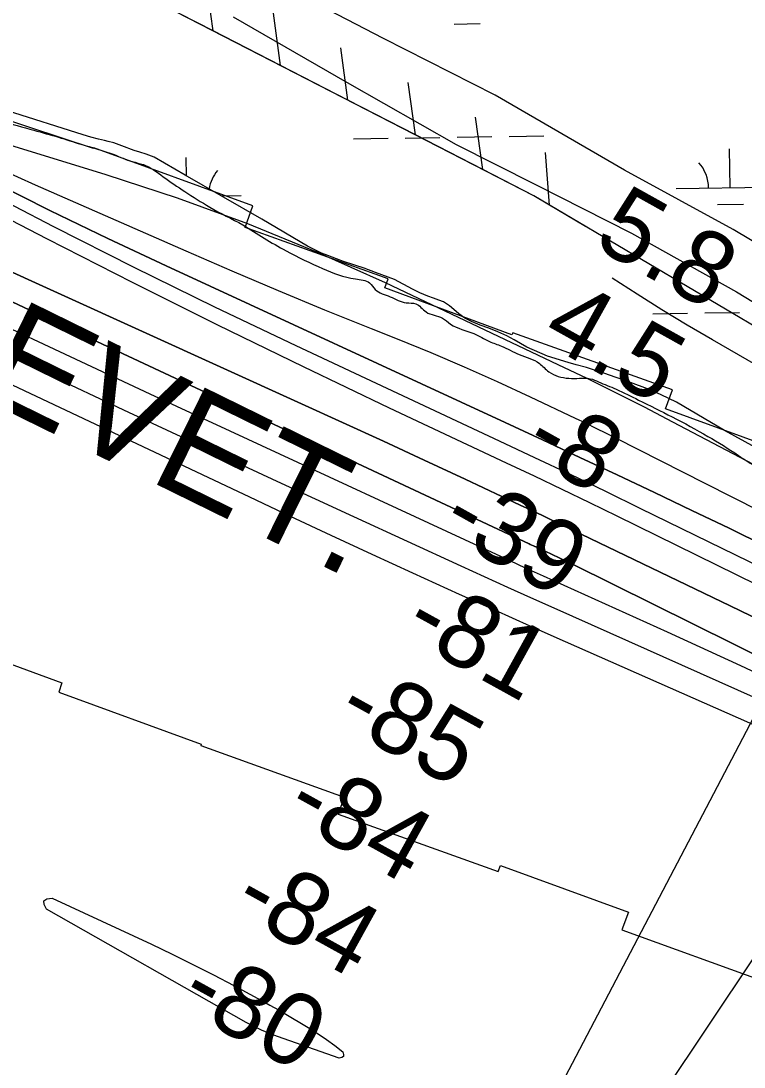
# Model space of a CAD drawing. Extents: x 3855477 to 3893699, y 299188 to 325115.
# Drawn here: x 3862374 to 3863042, y 315928 to 316895 of the extents above; entities that cross this region are included whole.
import ezdxf

# ---------------------------------------------------------------- set-up
doc = ezdxf.new("R2010")
doc.units = 0
for name, color, linetype in [('V-LEVE-TOET', 7, 'Continuous'), ('V-RIVR-EDGE', 7, 'Continuous'), ('V-RIVR-RANG', 7, 'Continuous'), ('V-ROAD-CNTR', 7, 'Continuous'), ('V-RRAP-FSHR', 7, 'Continuous'), ('V-RRAP-RVMT', 7, 'Continuous'), ('V-RRAP-RVMT-IDEN', 7, 'Continuous'), ('V-TOPO-DPTH', 7, 'Continuous'), ('V-TOPO-MAJR', 7, 'Continuous'), ('V-TOPO-MINR', 7, 'Continuous'), ('V-TOPO-WATR', 7, 'Continuous'), ('V-WETL-SWMP', 7, 'Continuous')]:
    doc.layers.add(name, color=color, linetype=linetype)

msp = doc.modelspace()

# ---------------------------------------------------------------- linework, layer by layer
at = {"layer": 'V-LEVE-TOET'}
for points in [[(3864365.02, 315977.84), (3864291.52, 316022.98), (3864202.21, 316071.98), (3864114.46, 316118.32), (3864011.47, 316172.75), (3863900.03, 316227.26), (3863792.82, 316282.79), (3863620.45, 316372.27), (3863488.09, 316447.6), (3863361.48, 316517.59), (3863231.7, 316587.09), (3863120.34, 316649.52), (3863032.12, 316702.21), (3862931.78, 316757.14), (3862812.04, 316826.53), (3862709.02, 316878.84), (3862581.85, 316945.14), (3862463.67, 317012.4), (3862350.14, 317069.05)], [(3862570.28, 316898.77), (3862675.32, 316837.98), (3862776.17, 316780.94), (3862848.7, 316744.26), (3862938.05, 316698.96), (3863035.23, 316644.59), (3863155.98, 316570.97), (3863261.65, 316519.68), (3863353.05, 316468.55), (3863460.76, 316410.37), (3863583.75, 316348.35), (3863677.77, 316295.6), (3863771.86, 316248.66), (3863851.78, 316211.38), (3863907.02, 316188.09), (3864001.5, 316127.94), (3864120.16, 316055.92), (3864180.06, 316024.66), (3864287.88, 315977.05), (3864332.62, 315960.74), (3864357.98, 315960.48), (3864374.39, 315963.48), (3864374.47, 315971.4), (3864365.02, 315977.84)]]:
    msp.add_lwpolyline(points, dxfattribs=at)
at = {"layer": 'V-RIVR-EDGE'}
for points in [[(3861643.53, 317089.49), (3861674.18, 317073.47), (3861698.46, 317060.26), (3861723.94, 317049.04), (3861744.63, 317038.63), (3861771.7, 317026.2), (3861804.75, 317012.17), (3861824.65, 317002.96), (3861840.97, 316994.15), (3861856.1, 316990.13), (3861866.47, 316990.1), (3861879.61, 316985.69), (3861900.3, 316974.08), (3861917.82, 316966.46), (3862001.43, 316931.98), (3862028.89, 316919.56), (3862036.87, 316919.94), (3862045.23, 316916.33), (3862058.76, 316907.93), (3862071.5, 316904.31), (3862089.42, 316899.08), (3862105.35, 316894.26), (3862127.64, 316884.64), (3862144.36, 316874.64), (3862154.31, 316868.24), (3862166.65, 316864.62), (3862190.95, 316859.78), (3862210.07, 316856.54), (3862236.75, 316848.9), (3862259.45, 316840.88), (3862302.44, 316817.65), (3862327.52, 316808.43), (3862335.49, 316808.41), (3862355.41, 316803.18), (3862386.07, 316793.93), (3862408.77, 316787.5), (3862429.48, 316781.07), (3862460.14, 316771.43), (3862476.86, 316765.01), (3862487.22, 316762.2), (3862505.52, 316751), (3862525.42, 316737.4), (3862548.5, 316722.99), (3862579.14, 316706.58)], [(3862579.14, 316706.58), (3862618.94, 316682.57), (3862652.77, 316666.14), (3862683.04, 316656.5), (3862696.18, 316652.88), (3862701.35, 316646.89), (3862715.28, 316640.08), (3862730.01, 316634.47), (3862738.78, 316633.65), (3862748.32, 316626.05), (3862763.45, 316620.43), (3862771.01, 316614.84), (3862792.51, 316606.02), (3862806.84, 316598.81), (3862817.99, 316594.4), (3862834.31, 316586.78), (3862853.02, 316578.37), (3862861.77, 316570.77), (3862880.08, 316564.75), (3862890.05, 316564.73), (3862900.01, 316564.3), (3862907.58, 316561.49), (3862923.9, 316554.68), (3862944.6, 316544.66), (3862975.64, 316529.04), (3863008.68, 316511.03), (3863036.93, 316493.42), (3863051.26, 316484.22), (3863059.61, 316479.82), (3863073.14, 316469.42), (3863078.7, 316461.84), (3863091.04, 316455.43), (3863113.73, 316446.6), (3863137.23, 316440.57), (3863166.3, 316430.53), (3863183.42, 316425.71), (3863207.7, 316412.1), (3863228, 316399.69), (3863238.35, 316395.68), (3863252.68, 316390.47), (3863259.44, 316385.27), (3863266.6, 316378.08), (3863269.37, 316370.9), (3863279.32, 316363.3), (3863294.44, 316355.69), (3863309.17, 316346.89), (3863343, 316331.26), (3863355.34, 316322.06), (3863380.4, 316304.47), (3863423.37, 316277.26), (3863452.02, 316258.46), (3863472.72, 316247.65), (3863532.42, 316214.82), (3863576.2, 316192.79), (3863612.02, 316173.97), (3863662.97, 316147.94), (3863701.98, 316129.91), (3863762.09, 316101.46), (3863803.49, 316080.64), (3863847.67, 316056.62), (3863876.33, 316044.19), (3863896.63, 316031.79), (3863917.72, 316020.58), (3863971.85, 315991.35), (3864020.81, 315966.12), (3864054.23, 315946.51), (3864091.65, 315926.89), (3864114.73, 315913.68), (3864131.85, 315906.86), (3864146.97, 315897.66), (3864174.04, 315883.64), (3864183.18, 315874.06), (3864194.33, 315870.44), (3864207.47, 315866.82), (3864224.19, 315858.81), (3864239.32, 315850.4), (3864262.4, 315839.98), (3864273.56, 315837.17), (3864288.68, 315830.35), (3864303.82, 315827.93), (3864315.37, 315825.11), (3864338.47, 315817.08), (3864360.77, 315810.65), (3864391.41, 315792.24), (3864418.87, 315776.23), (3864435.97, 315762.24), (3864459.04, 315741.86), (3864510.37, 315709.85), (3864535.44, 315695.84), (3864548.97, 315685.44), (3864561.3, 315675.85), (3864568.85, 315666.66), (3864582.37, 315656.66), (3864595.1, 315647.07), (3864600.67, 315641.08), (3864607.02, 315633.09), (3864612.59, 315626.3), (3864620.15, 315622.69), (3864637.27, 315615.88), (3864659.57, 315609.05), (3864678.28, 315601.03), (3864697.4, 315595.4), (3864745.56, 315571.77), (3864769.85, 315563.74), (3864787.37, 315555.73), (3864811.24, 315540.52), (3864821.2, 315537.71), (3864833.16, 315537.68), (3864842.32, 315536.46), (3864849.48, 315531.26), (3864857.43, 315522.87), (3864872.16, 315516.86), (3864908, 315506.01), (3864925.13, 315500.39), (3864937.87, 315498.76), (3864948.62, 315491.56), (3864956.98, 315489.55), (3864964.15, 315487.54), (3865017.51, 315468.28), (3865068.47, 315449.82), (3865096.34, 315439.39), (3865128.59, 315424.96), (3865154.87, 315414.93), (3865175.96, 315401.73), (3865212.19, 315385.7), (3865243.63, 315368.48), (3865263.13, 315356.48), (3865277.85, 315348.07), (3865296.96, 315338.06), (3865316.47, 315331.24), (3865337.16, 315318.04), (3865369.39, 315298.43), (3865405.2, 315275.22), (3865431.87, 315259.61), (3865448.19, 315254), (3865473.66, 315238.39), (3865499.13, 315224.78), (3865515.06, 315217.96), (3865531.77, 315209.15), (3865549.68, 315199.54), (3865571.18, 315191.52), (3865609, 315173.09), (3865653.97, 315145.48), (3865693.76, 315123.07), (3865732.77, 315101.85), (3865776.94, 315077.43), (3865798.43, 315063.82), (3865826.69, 315046.62), (3865853.35, 315032.6), (3865883.2, 315017.39), (3865895.15, 315011.38), (3865904.29, 315003.78), (3865913.04, 314994.59), (3865919.8, 314990.19), (3865927.77, 314987.38), (3865939.71, 314983.37), (3865950.47, 314980.55), (3865961.62, 314976.54), (3865977.53, 314967.34), (3866028.88, 314942.9), (3866056.75, 314928.48), (3866076.64, 314915.28), (3866096.53, 314901.68), (3866120.41, 314888.47), (3866143.9, 314878.05), (3866161.41, 314867.25), (3866178.14, 314862.82), (3866201.24, 314856.79), (3866223.14, 314850.36), (3866245.83, 314837.55), (3866263.73, 314827.14), (3866282.84, 314818.72), (3866292.41, 314818.7), (3866300.78, 314818.28), (3866309.94, 314816.27), (3866326.66, 314808.65), (3866348.53, 314791.06), (3866360.08, 314786.25), (3866377.59, 314778.64), (3866387.55, 314775.02), (3866394.31, 314767.44), (3866401.87, 314762.24), (3866413.81, 314757.03), (3866423.36, 314751.42), (3866432.12, 314749.81), (3866437.69, 314746.21), (3866445.65, 314739.41), (3866454.4, 314732.22), (3866485.45, 314718.99), (3866510.53, 314708.56), (3866533.21, 314691.37), (3866541.97, 314691.35), (3866549.94, 314690.93), (3866556.31, 314686.53), (3866561.87, 314678.55), (3866573.8, 314670.15), (3866598.9, 314663.71), (3866631.14, 314649.28), (3866660.61, 314640.44), (3866694.86, 314628.4), (3866748.2, 314604.36), (3866780.45, 314591.52), (3866811.1, 314575.51), (3866846.93, 314561.47), (3866895.5, 314539.03), (3866932.13, 314524.59), (3866954.81, 314513.38), (3866988.26, 314500.54), (3867018.51, 314486.52), (3867041.2, 314475.3), (3867068.66, 314458.5), (3867097.31, 314440.09), (3867123.99, 314432.46), (3867147.11, 314433.2), (3867169.41, 314427.96), (3867197.28, 314417.13), (3867215.2, 314410.71), (3867238.69, 314401.49), (3867251.43, 314396.27), (3867258.61, 314395.86), (3867271.36, 314397.42), (3867288.1, 314397.78), (3867302.45, 314396.15), (3867345.46, 314385.28), (3867427.5, 314359.57), (3867438.25, 314357.95), (3867445.03, 314357.93), (3867453.42, 314369.47), (3867458.24, 314381.41), (3867462.26, 314395.75), (3867462.28, 314404.12), (3867460.7, 314411.7), (3867457.12, 314414.1), (3867450.75, 314416.11), (3867442.78, 314416.52), (3867438.8, 314420.12), (3867443.19, 314422.1), (3867451.58, 314428.06), (3867458.77, 314437.21), (3867459.58, 314442.79), (3867460, 314450.75), (3867463.6, 314455.13), (3867470.8, 314463.88), (3867472, 314469.46), (3867472.42, 314477.03), (3867471.64, 314485), (3867465.71, 314504.54), (3867463.75, 314514.51), (3867463.37, 314524.48), (3867464.21, 314541.21), (3867469.07, 314571.09), (3867474.67, 314579.84), (3867478.26, 314581.43), (3867485.04, 314582.61), (3867525.27, 314574.94), (3867536.02, 314568.93), (3867545.17, 314565.72), (3867555.14, 314566.49), (3867569.88, 314566.06), (3867581.03, 314559.65), (3867584.99, 314552.07), (3867591.75, 314543.69), (3867611.65, 314532.88), (3867627.95, 314518.09), (3867650.21, 314493.33), (3867659.75, 314484.93), (3867663.31, 314472.97), (3867663.27, 314455.43), (3867660.06, 314447.47), (3867647.3, 314446.31), (3867632.15, 314444.75), (3867612.61, 314438.42), (3867582.29, 314425.34)]]:
    msp.add_spline(points, degree=3, dxfattribs=at)
at = {"layer": 'V-RIVR-RANG'}
msp.add_line((3863215.95, 316566.62), (3862844.67, 315858), dxfattribs=at)
at = {"layer": 'V-ROAD-CNTR'}
msp.add_lwpolyline([(3860065.6, 311560.18), (3863135.44, 316155.31)], dxfattribs=at)
at = {"layer": 'V-RRAP-FSHR'}
for p, q in [((3862551.71, 316885.84), (3862545.12, 316934.23)), ((3862613.95, 316853.8), (3862607.36, 316902.18)), ((3862676.18, 316821.75), (3862669.59, 316870.14)), ((3862738.41, 316789.71), (3862731.82, 316838.09)), ((3862800.65, 316757.67), (3862794.06, 316806.05)), ((3862862.4, 316724.76), (3862858.66, 316773.44))]:
    msp.add_line(p, q, dxfattribs=at)
for points in [[(3863755.9, 316222.32), (3863272.86, 316481.96), (3862847.86, 316733.36), (3862473.5, 316926.11), (3861935.6, 317229.54), (3861789.61, 317312.68)], [(3862551.71, 316885.84), (3862489.48, 316917.89)], [(3862613.95, 316853.8), (3862551.71, 316885.84)], [(3862676.18, 316821.75), (3862613.95, 316853.8)], [(3862738.41, 316789.71), (3862676.18, 316821.76)], [(3862800.65, 316757.67), (3862738.41, 316789.71)], [(3862862.4, 316724.76), (3862847.86, 316733.36), (3862800.65, 316757.67)], [(3862895.54, 316705.15), (3862862.4, 316724.76)]]:
    msp.add_lwpolyline(points, dxfattribs=at)
at = {"layer": 'V-RRAP-RVMT'}
for p, q in [((3862440.97, 316777.01), (3862309, 316820.54)), ((3862441.42, 316777.81), (3862440.97, 316777.01)), ((3862588.21, 316724.1), (3862441.42, 316777.81)), ((3862581.14, 316704.22), (3862588.21, 316724.1)), ((3862713.34, 316656.63), (3862581.14, 316704.22)), ((3862710.1, 316648.35), (3862713.34, 316656.63)), ((3862827.43, 316604.8), (3862710.1, 316648.35)), ((3862828.53, 316606.8), (3862827.43, 316604.8)), ((3862976.04, 316553.99), (3862828.53, 316606.8)), ((3862969.59, 316536.63), (3862976.04, 316553.99)), ((3863102.97, 316487.8), (3862969.59, 316536.63)), ((3862279.58, 316331.69), (3862411.96, 316283.18)), ((3862411.96, 316283.18), (3862409.05, 316274.73)), ((3862409.05, 316274.73), (3862540.6, 316226.59)), ((3862540.6, 316226.59), (3862540.19, 316225.31)), ((3862540.19, 316225.31), (3862672.72, 316177.65)), ((3862672.72, 316177.65), (3862667.13, 316161.85)), ((3862667.13, 316161.85), (3862814.8, 316108.78)), ((3862814.8, 316108.78), (3862816.98, 316114.47)), ((3862816.98, 316114.47), (3862935.42, 316071.43)), ((3862935.42, 316071.43), (3862929.29, 316055.02)), ((3862929.29, 316055.02), (3863061.95, 316006.79))]:
    msp.add_line(p, q, dxfattribs=at)
at = {"layer": 'V-TOPO-DPTH'}
for points in [[(3863477.33, 316165.73), (3862925, 316437.18), (3862899.51, 316449.63), (3862873.99, 316461.98), (3862848.4, 316474.21), (3862822.77, 316486.34), (3862714.62, 316537.21), (3862635.1, 316575.16), (3862555.88, 316613.71), (3862477.09, 316653.15), (3862398.61, 316693.2), (3862222.96, 316784.06)], [(3863477.33, 316165.73), (3862925, 316437.18), (3862899.51, 316449.63), (3862873.99, 316461.98), (3862848.4, 316474.21), (3862822.77, 316486.34), (3862714.62, 316537.21), (3862635.1, 316575.16), (3862555.88, 316613.71), (3862477.09, 316653.15), (3862398.61, 316693.2), (3862222.96, 316784.06)], [(3863687.1, 316156.12), (3863630.2, 316184.48), (3863620.72, 316189.22), (3863611.25, 316193.97), (3863601.79, 316198.74), (3863592.34, 316203.54), (3863510.78, 316245.01), (3863460.61, 316270.66), (3863410.5, 316296.44), (3863360.51, 316322.43), (3863310.58, 316348.55), (3862976.42, 316524.28), (3862950.08, 316537.92), (3862923.64, 316551.34), (3862897.03, 316564.42), (3862870.31, 316577.29), (3862710.79, 316652.88), (3862647.57, 316681.17), (3862583.62, 316707.59), (3862518.57, 316731.19), (3862452.8, 316752.91), (3862359.91, 316781.36)], [(3862347.54, 316746.73), (3862400.7, 316719.9), (3862454.28, 316693.92), (3862508.14, 316668.51), (3862821.29, 316523.8), (3862855.89, 316507.75), (3862890.45, 316491.62), (3862924.97, 316475.38), (3862959.44, 316459.06), (3862993.86, 316442.62), (3863028.22, 316426.07), (3863062.51, 316409.37), (3863096.76, 316392.57), (3863561.69, 316163.12), (3863574.79, 316156.63), (3863587.87, 316150.1), (3863600.93, 316143.53), (3863613.97, 316136.92), (3863986.61, 315947.23)], [(3862347.54, 316746.73), (3862400.7, 316719.9), (3862454.28, 316693.92), (3862508.14, 316668.51), (3862821.29, 316523.8), (3862855.89, 316507.75), (3862890.45, 316491.62), (3862924.97, 316475.38), (3862959.44, 316459.06), (3862993.86, 316442.62), (3863028.22, 316426.07), (3863062.51, 316409.37), (3863096.76, 316392.57), (3863561.69, 316163.12), (3863574.79, 316156.63), (3863587.87, 316150.1), (3863600.93, 316143.53), (3863613.97, 316136.92), (3863986.61, 315947.23)], [(3862339.28, 316674.71), (3862633.23, 316541.24), (3862671.07, 316523.97), (3862708.87, 316506.6), (3862746.6, 316489.08), (3862784.29, 316471.47), (3862835.29, 316447.51), (3862847.43, 316441.79), (3862859.57, 316436.04), (3862871.68, 316430.26), (3862883.79, 316424.46), (3863029.31, 316354.54), (3863114.03, 316313.48), (3863198.56, 316272.03), (3863282.8, 316230.01), (3863366.86, 316187.61), (3863500.88, 316119.43), (3863528.6, 316105.17), (3863556.23, 316090.73), (3863583.72, 316076.04), (3863611.12, 316061.17), (3863748.82, 315985.63)], [(3863748.82, 315985.63), (3863611.12, 316061.17), (3863583.72, 316076.04), (3863556.23, 316090.73), (3863528.6, 316105.17), (3863500.88, 316119.43), (3863366.86, 316187.61), (3863282.8, 316230.01), (3863198.56, 316272.03), (3863114.03, 316313.48), (3863029.31, 316354.54), (3862883.79, 316424.46), (3862871.68, 316430.26), (3862859.57, 316436.04), (3862847.43, 316441.79), (3862835.29, 316447.51), (3862784.29, 316471.47), (3862746.6, 316489.08), (3862708.87, 316506.6), (3862671.07, 316523.97), (3862633.23, 316541.24), (3862339.28, 316674.71)], [(3862340.76, 316647), (3862381.53, 316627.91), (3862843.66, 316411.69), (3862844.6, 316411.25), (3862847.43, 316409.94), (3862858.49, 316404.83), (3862864.96, 316401.81), (3862871.4, 316398.76), (3862877.82, 316395.65), (3862884.22, 316392.51), (3863512.75, 316080.95), (3863527.82, 316073.32), (3863542.79, 316065.53), (3863557.63, 316057.47), (3863572.38, 316049.25), (3864306.62, 315631.55)], [(3864306.62, 315631.55), (3863572.38, 316049.25), (3863557.63, 316057.47), (3863542.79, 316065.53), (3863527.82, 316073.32), (3863512.75, 316080.95), (3862884.22, 316392.51), (3862877.82, 316395.65), (3862871.4, 316398.76), (3862864.96, 316401.81), (3862858.49, 316404.83), (3862847.43, 316409.94), (3862844.6, 316411.25), (3862843.66, 316411.69), (3862381.53, 316627.91), (3862340.76, 316647)]]:
    msp.add_lwpolyline(points, dxfattribs=at)
at = {"layer": 'V-TOPO-MAJR'}
msp.add_lwpolyline([(3863893.33, 315853.22), (3863557.11, 316044.81), (3863547.33, 316050.26), (3863537.5, 316055.6), (3863527.58, 316060.76), (3863517.59, 316065.8), (3863241.6, 316202.07), (3863174.37, 316234.84), (3863106.94, 316267.17), (3863039.19, 316298.83), (3862971.23, 316330.04), (3862856.68, 316381.97), (3862845.84, 316386.9), (3862835.01, 316391.85), (3862824.19, 316396.82), (3862813.38, 316401.81), (3862567.32, 316515.77), (3862493.51, 316550.04), (3862419.74, 316584.41), (3862346.04, 316618.92)], dxfattribs=at)
at = {"layer": 'V-TOPO-MINR'}
for points in [[(3863477.33, 316165.73), (3862925, 316437.18), (3862899.51, 316449.63), (3862873.99, 316461.98), (3862848.4, 316474.21), (3862822.77, 316486.34), (3862714.62, 316537.21), (3862635.1, 316575.16), (3862555.88, 316613.71), (3862477.09, 316653.15), (3862398.61, 316693.2), (3862222.96, 316784.06)], [(3863056.53, 316441.88), (3863006.14, 316467.41), (3862924.37, 316508.98), (3862914.88, 316513.75), (3862905.36, 316518.47), (3862895.81, 316523.11), (3862886.23, 316527.7), (3862844.81, 316547.33), (3862814.38, 316561.4), (3862783.77, 316575.07), (3862752.91, 316588.16), (3862721.88, 316600.86), (3862697.92, 316610.39), (3862654.88, 316627.79), (3862611.96, 316645.49), (3862569.23, 316663.63), (3862526.62, 316682.08), (3862387.54, 316743.16), (3862354.86, 316757.94)], [(3863986.61, 315947.23), (3863613.97, 316136.92), (3863600.93, 316143.53), (3863587.87, 316150.1), (3863574.79, 316156.63), (3863561.69, 316163.12), (3863096.76, 316392.57), (3863062.51, 316409.37), (3863028.22, 316426.07), (3862993.86, 316442.62), (3862959.44, 316459.06), (3862924.97, 316475.38), (3862890.45, 316491.62), (3862855.89, 316507.75), (3862821.29, 316523.8), (3862508.14, 316668.51), (3862454.28, 316693.92), (3862400.7, 316719.9), (3862347.54, 316746.73)], [(3864294.09, 315759.78), (3863586.33, 316128.15), (3863582.35, 316130.21), (3863578.36, 316132.26), (3863574.37, 316134.3), (3863570.38, 316136.33), (3863472.39, 316185.8), (3863419.35, 316212.45), (3863366.24, 316238.95), (3863313.02, 316265.24), (3863259.73, 316291.4), (3862946.85, 316444.17), (3862914.25, 316459.98), (3862881.61, 316475.7), (3862848.89, 316491.25), (3862816.13, 316506.7), (3862628.22, 316594.74), (3862553.23, 316630.53), (3862478.59, 316667.03), (3862404.48, 316704.59), (3862330.72, 316742.86)], [(3863714.8, 315941.65), (3863653.97, 315976.39), (3863541.84, 316040.39), (3863537.04, 316043.07), (3863532.22, 316045.69), (3863527.34, 316048.21), (3863522.44, 316050.68), (3863429.88, 316096.21), (3863378.54, 316121.11), (3863327.02, 316145.62), (3863275.22, 316169.55), (3863223.24, 316193.1), (3862866.71, 316352.19), (3862845.2, 316361.83), (3862823.71, 316371.52), (3862802.25, 316381.29), (3862780.81, 316391.1), (3862681.74, 316436.65), (3862610.84, 316469.38), (3862539.99, 316502.24), (3862469.25, 316535.32), (3862398.57, 316568.53), (3862135.83, 316692.45)], [(3863466.95, 316060.89), (3862877.26, 316321.18), (3862844.56, 316335.69), (3862811.9, 316350.29), (3862779.3, 316365.02), (3862746.74, 316379.83), (3862736.2, 316384.66), (3862698.43, 316402.02), (3862660.7, 316419.47), (3862623.04, 316437.06), (3862585.42, 316454.74), (3862103.1, 316682.52)], [(3863748.82, 315985.63), (3863611.12, 316061.17), (3863583.72, 316076.04), (3863556.23, 316090.73), (3863528.6, 316105.17), (3863500.88, 316119.43), (3863366.86, 316187.61), (3863282.8, 316230.01), (3863198.56, 316272.03), (3863114.03, 316313.48), (3863029.31, 316354.54), (3862883.79, 316424.46), (3862871.68, 316430.26), (3862859.57, 316436.04), (3862847.43, 316441.79), (3862835.29, 316447.51), (3862784.29, 316471.47), (3862746.6, 316489.08), (3862708.87, 316506.6), (3862671.07, 316523.97), (3862633.23, 316541.24), (3862339.28, 316674.71)], [(3864412.89, 315889.33), (3863957.17, 316123.81), (3863906.82, 316149.3), (3863856.24, 316174.33), (3863805.33, 316198.69), (3863754.21, 316222.59), (3863683.71, 316254.98), (3863667.69, 316262.4), (3863651.71, 316269.9), (3863635.77, 316277.49), (3863619.87, 316285.16), (3863376.75, 316403.41), (3863306.95, 316438.26), (3863237.66, 316474.06), (3863169.13, 316511.3), (3863101.1, 316549.49), (3863012.98, 316600.17), (3862989.52, 316613.95), (3862966.24, 316628.01), (3862943.23, 316642.49), (3862920.38, 316657.26)], [(3864306.62, 315631.55), (3863572.38, 316049.25), (3863557.63, 316057.47), (3863542.79, 316065.53), (3863527.82, 316073.32), (3863512.75, 316080.95), (3862884.22, 316392.51), (3862877.82, 316395.65), (3862871.4, 316398.76), (3862864.96, 316401.81), (3862858.49, 316404.83), (3862847.43, 316409.94), (3862844.6, 316411.25), (3862843.66, 316411.69), (3862381.53, 316627.91), (3862340.76, 316647)], [(3862608.08, 315983.29), (3862611.97, 315981.05), (3862615.85, 315978.78), (3862640.81, 315963.95), (3862648.74, 315958.98), (3862656.5, 315953.75), (3862663.99, 315948.15), (3862671.3, 315942.3), (3862672.18, 315939.86), (3862672.07, 315937.97), (3862670.5, 315936.93), (3862667.96, 315936.44), (3862611.02, 315956.42), (3862603.63, 315959.23), (3862596.36, 315962.31), (3862589.26, 315965.77), (3862582.28, 315969.48), (3862397.62, 316074.21), (3862395.51, 316078.53), (3862395.35, 316081.84), (3862398.13, 316083.63), (3862402.88, 316084.41), (3862494.69, 316041.62), (3862513.88, 316032.48), (3862532.96, 316023.11), (3862551.87, 316013.42), (3862570.68, 316003.52), (3862600.21, 315987.63), (3862604.15, 315985.48), (3862608.08, 315983.29)]]:
    msp.add_lwpolyline(points, dxfattribs=at)
at = {"layer": 'V-TOPO-WATR'}
msp.add_lwpolyline([(3863687.1, 316156.12), (3863630.2, 316184.48), (3863620.72, 316189.22), (3863611.25, 316193.97), (3863601.79, 316198.74), (3863592.34, 316203.54), (3863510.78, 316245.01), (3863460.61, 316270.66), (3863410.5, 316296.44), (3863360.51, 316322.43), (3863310.58, 316348.55), (3862976.42, 316524.28), (3862950.08, 316537.92), (3862923.64, 316551.34), (3862897.03, 316564.42), (3862870.31, 316577.29), (3862710.79, 316652.88), (3862647.57, 316681.17), (3862583.62, 316707.59), (3862518.57, 316731.19), (3862452.8, 316752.91), (3862359.91, 316781.36)], dxfattribs=at)
at = {"layer": 'V-WETL-SWMP'}
for p, q in [((3862774.3, 316892.15), (3862798.3, 316892.54)), ((3862681.17, 316785.98), (3862713.17, 316786.5)), ((3862729.17, 316786.76), (3862761.16, 316787.28)), ((3862777.16, 316787.55), (3862809.16, 316788.07)), ((3862825.15, 316788.33), (3862857.15, 316788.85)), ((3863029.27, 316740.9), (3863028.68, 316776.9)), ((3862527.12, 316751.67), (3862526.84, 316768.72)), ((3862979.28, 316740.09), (3863079.26, 316741.72)), ((3862559.19, 316733.25), (3862577.42, 316733.54)), ((3863017.52, 316725.28), (3863041.52, 316725.67)), ((3862957.75, 316624.29), (3862989.75, 316624.81)), ((3863005.75, 316625.07), (3863037.74, 316625.59))]:
    msp.add_line(p, q, dxfattribs=at)
for points in [[(3862672.07, 316672.76), (3862665.57, 316675.13), (3862657.73, 316678.09), (3862651.8, 316680.45), (3862638.82, 316686.92), (3862596.66, 316711.73), (3862525.87, 316752.38), (3862497.06, 316769), (3862489.61, 316771.95), (3862484.06, 316773.74), (3862478.7, 316775.33), (3862467.42, 316779.67), (3862459.96, 316782.24), (3862454.8, 316783.64), (3862451.16, 316784.44), (3862445.61, 316785.65), (3862438.52, 316787.64), (3862431.64, 316789.63), (3862361.62, 316812.04)], [(3863071.7, 316490.14), (3863023.99, 316516.54), (3862979.73, 316542.53), (3862965.41, 316549.58), (3862955.28, 316553.91), (3862934.63, 316561.61), (3862922.96, 316565.76), (3862913.4, 316569.12), (3862904.79, 316571.9), (3862896.38, 316574.67), (3862887, 316577.26), (3862879.73, 316579.26), (3862860.6, 316585.02), (3862841.3, 316593.47), (3862829.85, 316600.12), (3862822.98, 316603.83), (3862814.58, 316607.76), (3862806.35, 316610.91), (3862798.32, 316613.88), (3862790.3, 316617.22), (3862784.19, 316620.36), (3862778.66, 316624.25), (3862773.91, 316628.33), (3862769.91, 316631.83), (3862764.38, 316635.34), (3862760.18, 316636.92), (3862755.2, 316638.7), (3862749.85, 316640.67), (3862742.59, 316643.82), (3862735.71, 316646.96), (3862719.11, 316656.15), (3862701.52, 316662.48), (3862691, 316666.42), (3862682.4, 316669.2), (3862672.07, 316672.76)]]:
    msp.add_lwpolyline(points, dxfattribs=at)
for centre, start, end in [((3862582.66, 316734.1), 140.16154, 170.77694), ((3862974.03, 316740.48), 0.16154, 41.7052)]:
    msp.add_arc(centre, 35.25, start, end, dxfattribs=at)

# ---------------------------------------------------------------- texts
at = {"layer": 'V-RIVR-RANG'}
for s, rotation, p in [('5.8', 330.80833, (3862901.28, 316687.31)), ('4.5', 330.80833, (3862852.72, 316599.89)), ('-8', 330.80833, (3862835.25, 316495.1)), ('-39', 330.80833, (3862758.83, 316423.25)), ('-81', 331.09031, (3862724.53, 316327.5)), ('-85', 331.09031, (3862662.35, 316247.6)), ('-84', 331.09031, (3862615.41, 316159.29)), ('-84', 331.09031, (3862566.85, 316071.87)), ('-80', 331.09031, (3862517.36, 315984.96))]:
    msp.add_text(s, height=67, rotation=rotation, dxfattribs=at).set_placement(p)
at = {"layer": 'V-RRAP-RVMT-IDEN'}
msp.add_text('REVET.', height=100, rotation=333.82987, dxfattribs=at).set_placement((3862243.14, 316592.55))

doc.saveas('drawing.dxf')
